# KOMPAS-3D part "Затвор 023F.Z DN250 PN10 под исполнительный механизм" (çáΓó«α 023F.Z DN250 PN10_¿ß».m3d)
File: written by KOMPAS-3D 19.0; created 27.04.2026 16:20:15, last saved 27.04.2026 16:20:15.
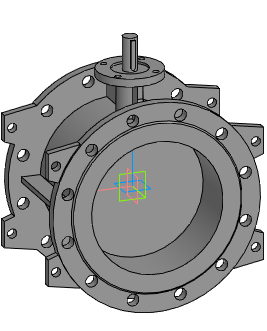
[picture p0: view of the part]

Document properties: Автор: Евгений; Полное имя файла: Z:\3.Личные\kachalov\3d для проектировщиков\1.7 Тип 023F.Z Затвор дисковый поворотный фланцевый с двумя эксцентриками\Затвор 023F.Z DN200-DN1600_исп\_stp_Затвор 023F.Z DN200-DN1600_исп\Затвор 023F.Z DN250 PN10_исп.m3d

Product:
- Part/product: Затвор 023F.Z DN250 PN10 под исполнительный механизм

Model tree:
1. Операция без истории:1  (labels: Затвор 023F.Z DN250 PN10 под исполнительный механизм)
